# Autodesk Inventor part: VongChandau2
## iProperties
Created: 2011-05
Part Number: VongChandau2
Document SubType Name: Modeling
Designer: 904Chiaki
Density: 1 g/cm^3
Mass: 53.4941 g
Surface Area: 225.023 cm^2
Volume: 53.4941 cm^3
Author: 904Chiaki
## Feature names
1. Revolution1
